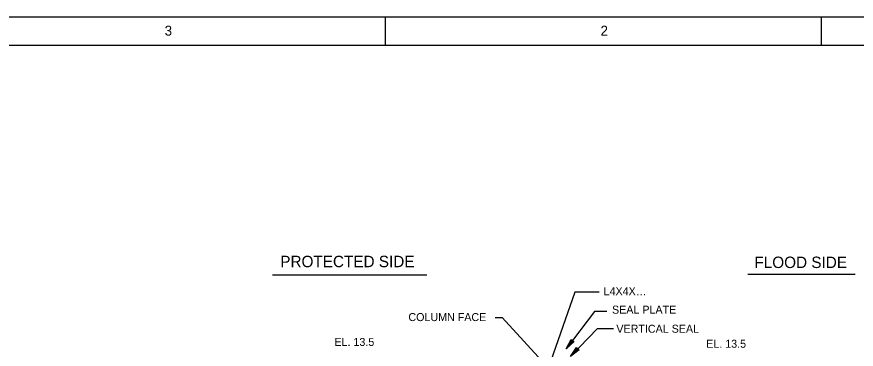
# Model space of a CAD drawing. Extents: x 0 to 320, y -4 to 473.
# Drawn here: x 17.8 to 32.48, y 22.18 to 28 of the extents above; entities that cross this region are included whole.
import ezdxf

# ---------------------------------------------------------------- set-up
doc = ezdxf.new("R2010")
doc.units = 0
for name, color, linetype in [('Level 1', 7, 'Continuous'), ('Level 10', 7, 'Continuous'), ('Level 3', 7, 'Continuous'), ('Level 50', 7, 'Continuous')]:
    doc.layers.add(name, color=color, linetype=linetype)

msp = doc.modelspace()

# ---------------------------------------------------------------- linework, layer by layer
at = {"layer": 'Level 1'}
for p, q in [((24.25, 27.5), (24.25, 28)), ((31.875, 27.5), (31.875, 28))]:
    msp.add_line(p, q, dxfattribs=at)
for points in [[(0, 28), (40, 28), (40, 0), (0, 0)], [(1.5, 27.5), (39.5, 27.5), (39.5, 0.5), (1.5, 0.5)]]:
    msp.add_lwpolyline(points, close=True, dxfattribs=at)
at = {"layer": 'Level 10'}
for points in [[(27.56, 23.175), (27.141, 21.977)], [(27.987, 23.175), (27.56, 23.175)], [(27.909, 22.839), (27.41, 22.183)], [(28.121, 22.839), (27.909, 22.839)], [(26.169, 22.734), (26.292, 22.734), (27.363, 21.562)], [(27.952, 22.537), (27.486, 22.053)], [(28.236, 22.537), (27.952, 22.537)]]:
    msp.add_lwpolyline(points, dxfattribs=at)
at = {"layer": 'Level 3'}
for p, q in [((22.274, 23.481), (24.975, 23.481)), ((30.588, 23.493), (32.467, 23.493))]:
    msp.add_line(p, q, dxfattribs=at)
at = {"layer": 'Level 50'}
for p, q in [((27.41, 22.183), (27.41, 22.183)), ((27.442, 22.224), (27.442, 22.224))]:
    msp.add_line(p, q, dxfattribs=at)
for points in [[(27.548, 22.313), (27.41, 22.183), (27.499, 22.35), (27.541, 22.318), (27.442, 22.224), (27.502, 22.338), (27.529, 22.317), (27.472, 22.264), (27.505, 22.326), (27.516, 22.317), (27.504, 22.305)], [(27.638, 22.166), (27.486, 22.053), (27.593, 22.209), (27.631, 22.172), (27.522, 22.09), (27.595, 22.196), (27.619, 22.173), (27.556, 22.126), (27.596, 22.184), (27.606, 22.174), (27.592, 22.164)]]:
    msp.add_lwpolyline(points, dxfattribs=at)

# ---------------------------------------------------------------- texts
at = {"layer": 'Level 1'}
for s, p in [('3', (20.387, 27.669)), ('2', (28.012, 27.669))]:
    msp.add_text(s, height=0.175, dxfattribs=at).set_placement(p)
at = {"layer": 'Level 10'}
for s, p in [('L4X4X…', (28.066, 23.124)), ('SEAL PLATE', (28.213, 22.801)), ('COLUMN FACE', (24.651, 22.671)), ('VERTICAL SEAL', (28.289, 22.467)), ('EL. 13.5', (23.357, 22.236)), ('EL. 13.5', (29.86, 22.204))]:
    msp.add_text(s, height=0.14, dxfattribs=at).set_placement(p)
at = {"layer": 'Level 3'}
for s, p in [('PROTECTED SIDE', (22.41, 23.615)), ('FLOOD SIDE', (30.704, 23.6))]:
    msp.add_text(s, height=0.2, dxfattribs=at).set_placement(p)

doc.saveas('drawing.dxf')
